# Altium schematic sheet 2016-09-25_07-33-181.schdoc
size 334 x 177 mm; SheetNumber: 1; SheetTotal: 1
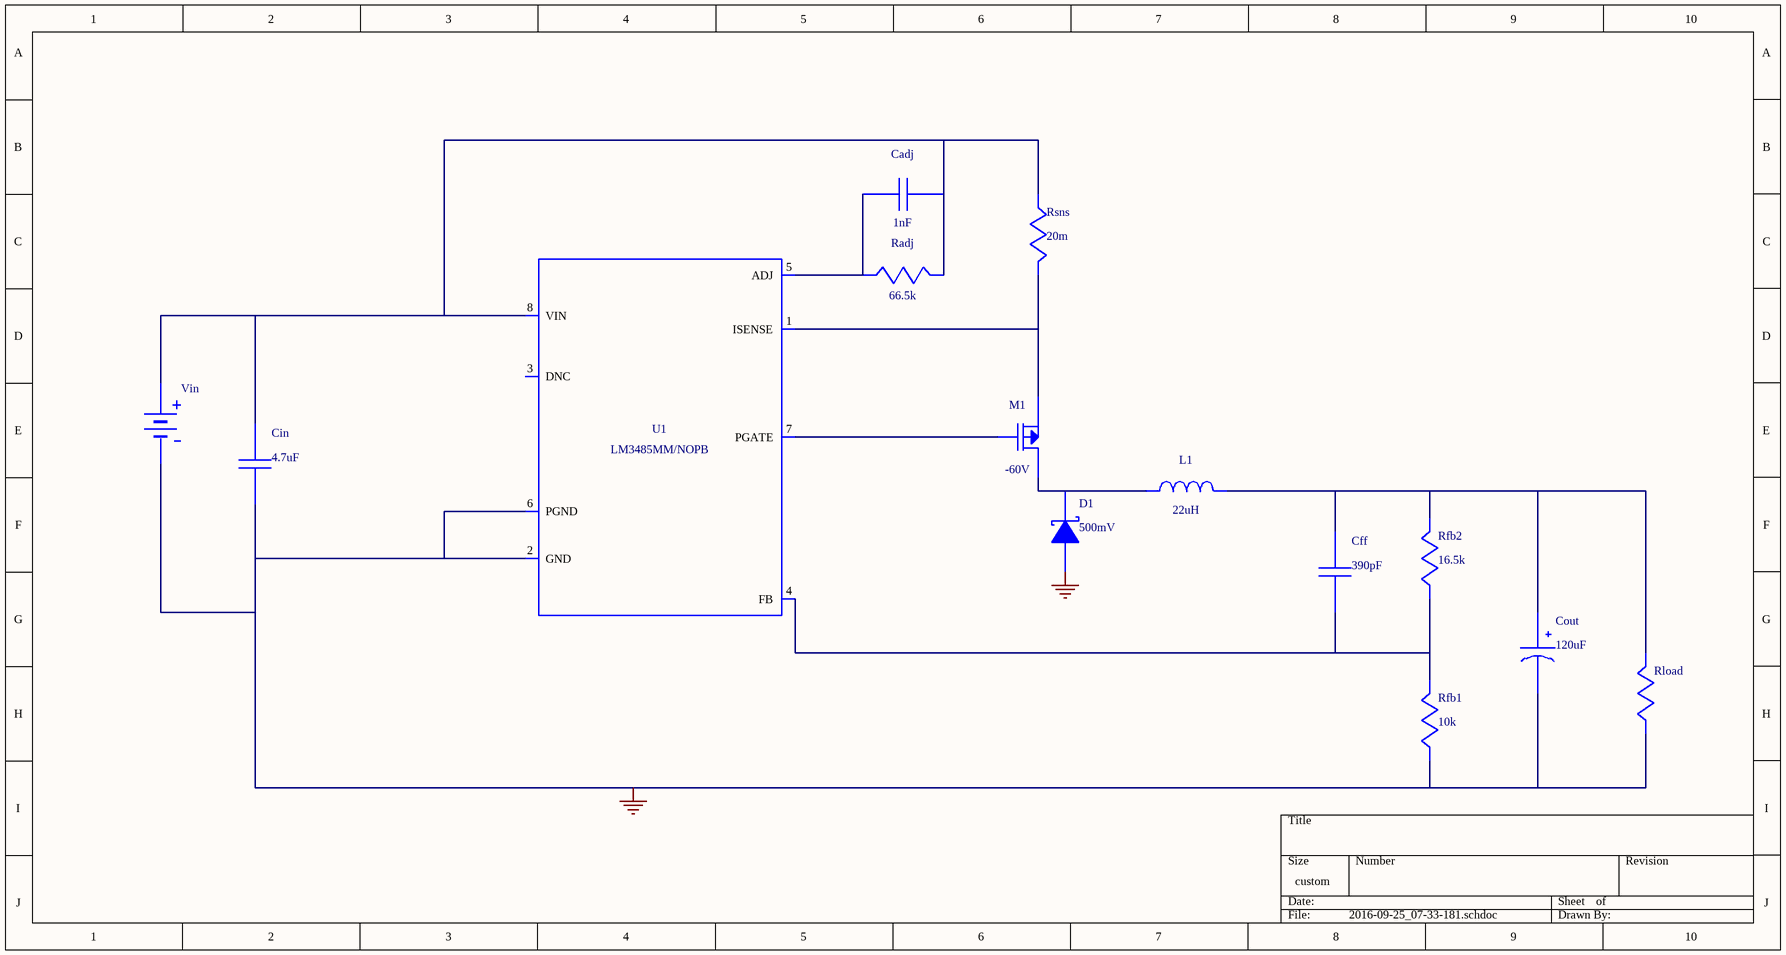
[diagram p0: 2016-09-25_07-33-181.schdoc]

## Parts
Cadj  value 1nF  (hidden comment: CL21C102JBCNFNC)
Cff  value 390pF  (hidden comment: CC0805KRX7R9BB391)
Cin  value 4.7uF  (hidden comment: GRM31CR71H475KA12L)
Cout  value 120uF  (hidden comment: 10SVP120M)
D1  value 500mV  (hidden comment: B340A-13-F)
L1  value 22uH  (hidden comment: SDR1307-220ML)
M1  value -60V  (hidden comment: FDC5614P)
Radj  value 66.5k  (hidden comment: CRCW040266K5FKED)
Rfb1  value 10k  (hidden comment: CRCW040210K0FKED)
Rfb2  value 16.5k  (hidden comment: CRCW040216K5FKED)
Rload  WB_LOAD_RESISTOR  (value not drawn)
Rsns  value 20m  (hidden comment: CSR1206FK20L0)
U1  LM3485MM/NOPB
Vin  WB_BATTERY  (value not drawn)

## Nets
0: Cin.2 Cout.2(-) D1.2(A) Rfb1.2 Rload.2 U1.2(GND) U1.6(PGND) Vin.2(-)
NetCadj_1: Cadj.1 Cin.1 Radj.1 Rsns.2 U1.8(VIN) Vin.1(+)
NetCadj_2: Cadj.2 Radj.2 U1.5(ADJ)
NetCff_1: Cff.1 Cout.1(+) L1.2 Rfb2.1 Rload.1
NetCff_2: Cff.2 Rfb1.1 Rfb2.2 U1.4(FB)
NetD1_1: D1.1(K) L1.1 M1.1(Drain) M1.2(Drain) M1.5(Drain) M1.6(Drain)
NetM1_3: M1.3(Gate) U1.7(PGATE)
NetM1_4: M1.4(Source) Rsns.1 U1.1(ISENSE)

Not connected (* = marked no-connect by the designer): U1 3(DNC)

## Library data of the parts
Cadj = CL21C102JBCNFNC: Manufacturer Name: Samsung Electro-Mechanics
Cff = CC0805KRX7R9BB391: CC0805KRX7R9BB39; Manufacturer Name: Yageo America
Cin = GRM31CR71H475KA12L: GRM31CR71H475KA1; Manufacturer Name: MuRata
Cout = 10SVP120M: Manufacturer Name: Panasonic
D1 = B340A-13-F: Manufacturer Name: Diodes Inc.
L1 = SDR1307-220ML: Manufacturer Name: Bourns
M1 = FDC5614P: Manufacturer Name: Fairchild Semiconductor
Radj = CRCW040266K5FKED: Manufacturer Name: Vishay-Dale
Rfb1 = CRCW040210K0FKED: Manufacturer Name: Vishay-Dale
Rfb2 = CRCW040216K5FKED: Manufacturer Name: Vishay-Dale
Rsns = CSR1206FK20L0: Manufacturer Name: Stackpole Electronics Inc
U1 = LM3485MM/NOPB: Manufacturer Name: Texas Instruments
